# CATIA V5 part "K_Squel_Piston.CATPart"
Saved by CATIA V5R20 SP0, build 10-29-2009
Part number: Squelette_piston
Publications: "Plan.10"
Bounding box of the stored display mesh (mm): x -38 to -18, y 169.401 to 196.271, z -180.312 to -129.401
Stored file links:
  G:\Khaled_CFAO_2011\ST2M\ST2M_GR2\plakomicki\Khaled\CAD_ThinkMOTION\K_Squel_Piston.CATPart
  G:\Khaled_CFAO_2011\ST2M\ST2M_GR2\plakomicki\Khaled\CAD_ThinkMOTION\K_Squelette.CATProduct
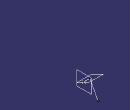
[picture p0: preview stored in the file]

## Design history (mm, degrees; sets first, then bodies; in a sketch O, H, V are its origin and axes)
Set1
  Plane1: linked copy from another document
  Plane2: linked copy from another document
  Point1: linked copy from another document
  Point2: linked copy from another document
  Plane3: linked copy from another document
Set2
  Plane4: type Offset, RefPlane Plane1, Offset 20
  Point3: type OnPlane, Support Plane4, RefPoint Point2, H 0, V 0, Direction (0, 1, 0)
  Line1: type PtPt, FirstPoint Point3, SecondPoint Point2
  Line2: type PtPt, FirstPoint Point1, SecondPoint Point2
  Plane5: type Normal, Curve Line2, RefPoint Point2
Body1 (main body)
